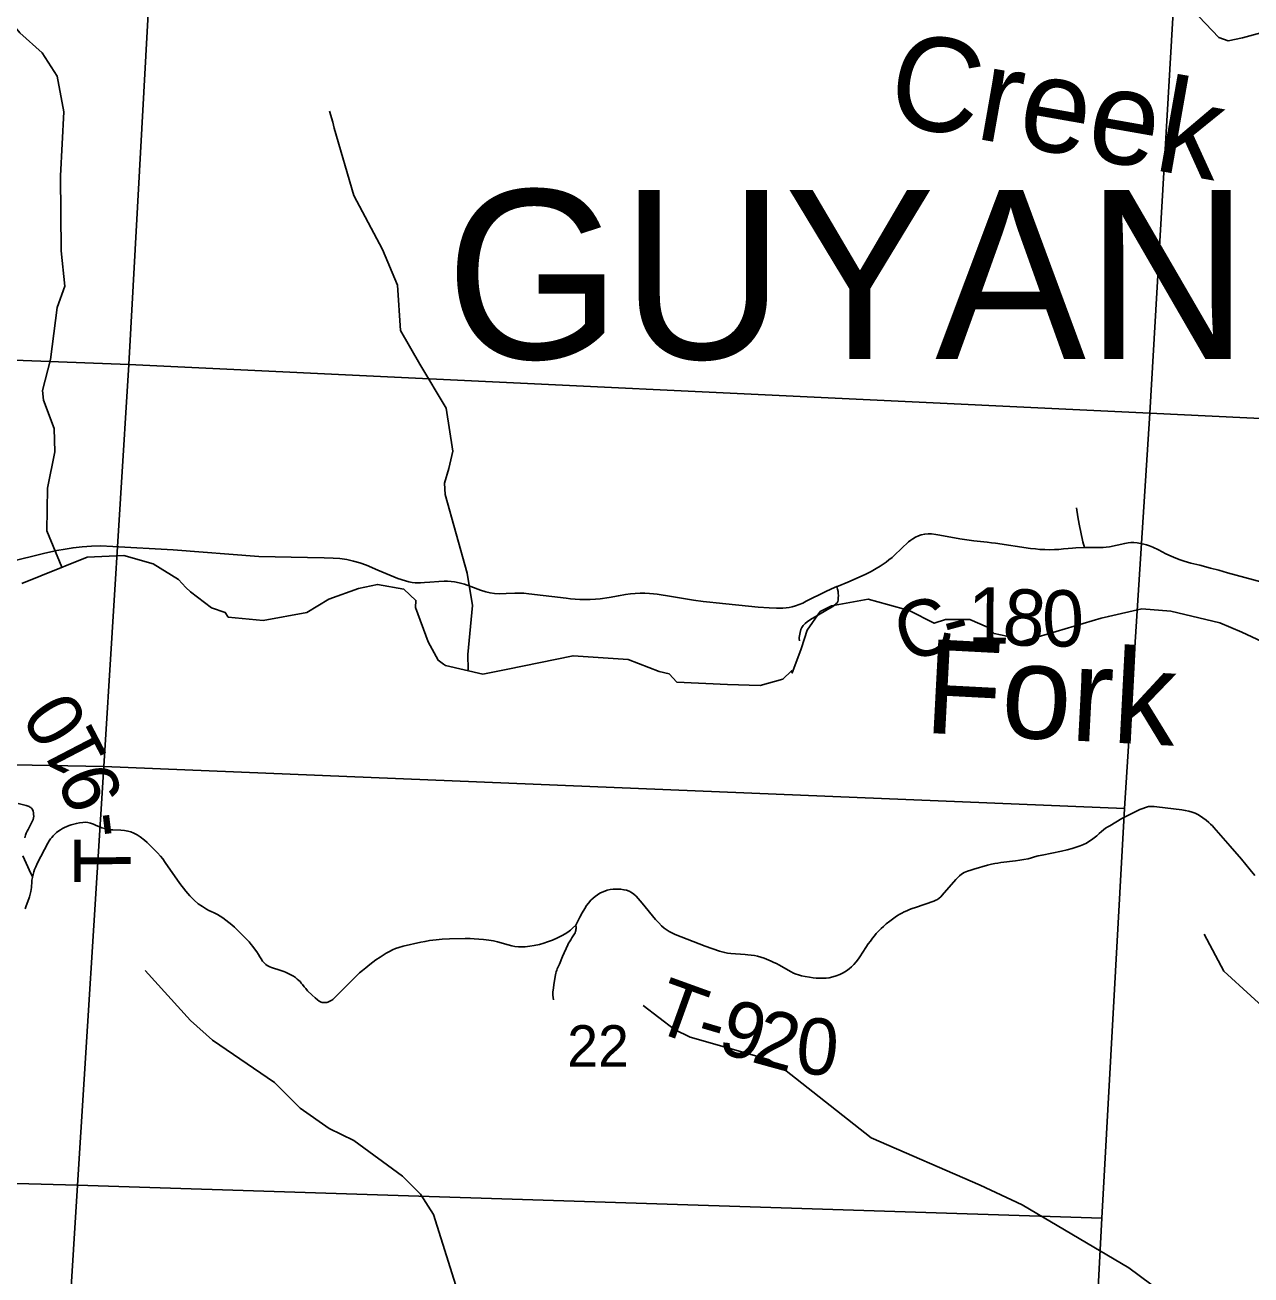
# Model space of a CAD drawing. Extents: x 0 to 34, y 0 to 22.
# Drawn here: x 25.071 to 26.308, y 17.66 to 18.921 of the extents above; entities that cross this region are included whole.
import ezdxf

# ---------------------------------------------------------------- set-up
doc = ezdxf.new("R2010")
doc.units = 0
for name, color, linetype in [('GM_X_County_Road', 7, 'Continuous'), ('GM_X_County_Road_Text', 7, 'Continuous'), ('GM_X_Minor_River', 7, 'Continuous'), ('GM_X_Minor_River_Text', 7, 'Continuous'), ('GM_X_Section', 7, 'Continuous'), ('GM_X_Section_Text', 7, 'Continuous'), ('GM_X_Township_Road', 7, 'Continuous'), ('GM_X_Township_Road_Text', 7, 'Continuous'), ('GM_X_Township_Text', 7, 'Continuous')]:
    doc.layers.add(name, color=color, linetype=linetype)

msp = doc.modelspace()

# ---------------------------------------------------------------- linework, layer by layer
at = {"layer": 'GM_X_County_Road'}
for points in [[(25.3731, 18.3836), (25.3822, 18.3832), (25.3889, 18.3827), (25.396, 18.3818), (25.4027, 18.3802), (25.4091, 18.3783), (25.4161, 18.3759), (25.4275, 18.371), (25.4476, 18.3627), (25.4553, 18.3602), (25.4586, 18.3594), (25.462, 18.3586), (25.4651, 18.3583), (25.4679, 18.3581), (25.4705, 18.3582), (25.4743, 18.3584), (25.48, 18.3588), (25.4888, 18.3596), (25.4943, 18.3599), (25.4975, 18.3599), (25.5012, 18.3597), (25.5046, 18.3592), (25.5094, 18.3583), (25.5147, 18.3568), (25.5211, 18.3546), (25.531, 18.3507), (25.5363, 18.349), (25.5406, 18.3481), (25.545, 18.3475), (25.55, 18.3472), (25.5569, 18.3474), (25.5656, 18.3479), (25.5703, 18.3479), (25.5748, 18.3477), (25.5797, 18.3472), (25.6173, 18.3426), (25.6217, 18.3422), (25.6265, 18.3417), (25.6313, 18.3415), (25.6369, 18.3414), (25.6416, 18.3414), (25.6468, 18.3416), (25.6517, 18.3421), (25.6608, 18.3435), (25.67, 18.3452), (25.6773, 18.3464), (25.6824, 18.3471), (25.6871, 18.3475), (25.6919, 18.3478), (25.6966, 18.3478), (25.7013, 18.3476), (25.7054, 18.3472), (25.7092, 18.3467), (25.7236, 18.3444), (25.7459, 18.3409), (25.7554, 18.3395), (25.7623, 18.3387), (25.7685, 18.338), (25.8109, 18.3338), (25.822, 18.3331), (25.8294, 18.3327), (25.8324, 18.3327), (25.8359, 18.3328), (25.8393, 18.3331), (25.8424, 18.3335), (25.8454, 18.334), (25.8487, 18.335), (25.8523, 18.3362), (25.856, 18.3378), (25.8595, 18.3396), (25.8794, 18.3495), (25.8843, 18.3519), (25.8882, 18.3536), (25.8905, 18.3545), (25.8919, 18.355), (25.9015, 18.3588), (25.9188, 18.3666), (25.9249, 18.3698), (25.9302, 18.3727), (25.9341, 18.375), (25.937, 18.377), (25.94, 18.3791), (25.943, 18.3813), (25.9461, 18.3837), (25.9486, 18.386), (25.9628, 18.3995), (25.9649, 18.4012), (25.9669, 18.4026), (25.9696, 18.4044), (25.9727, 18.4058), (25.9756, 18.4068), (25.979, 18.4074), (25.9825, 18.4076), (25.986, 18.4075), (25.9902, 18.407), (25.9944, 18.4062), (26.0146, 18.4025), (26.0287, 18.4006), (26.0419, 18.3992), (26.0463, 18.3987), (26.0505, 18.3981), (26.0856, 18.3929), (26.0908, 18.3924), (26.0953, 18.392), (26.1001, 18.3917), (26.1052, 18.3916), (26.1099, 18.3917), (26.1144, 18.392), (26.1191, 18.3924), (26.1239, 18.393), (26.1282, 18.3933), (26.1316, 18.3936), (26.1401, 18.3938), (26.156, 18.3939), (26.159, 18.394), (26.1622, 18.3943), (26.1654, 18.3947), (26.1808, 18.398), (26.1841, 18.3985), (26.1871, 18.3988), (26.19, 18.3988), (26.1932, 18.3985), (26.1968, 18.398), (26.2, 18.3973), (26.2028, 18.3965), (26.2058, 18.3954), (26.209, 18.3942), (26.2147, 18.3916), (26.2223, 18.3876), (26.2278, 18.385), (26.2323, 18.3831), (26.2366, 18.3815), (26.2408, 18.38), (26.2475, 18.3782), (26.2564, 18.376), (26.2673, 18.3731), (26.2756, 18.3709), (26.2845, 18.3684), (26.3282, 18.3564)], [(25.056, 18.3795), (25.0902, 18.3878), (25.1035, 18.3907), (25.112, 18.3923), (25.12, 18.3937), (25.1292, 18.3947), (25.1384, 18.3953), (25.1477, 18.3954), (25.1601, 18.395), (25.2208, 18.3915), (25.3075, 18.3848), (25.3566, 18.3838), (25.3731, 18.3836)]]:
    msp.add_lwpolyline(points, dxfattribs=at)
at = {"layer": 'GM_X_Minor_River'}
for points in [[(25.1087, 18.3739), (25.0935, 18.4107), (25.0941, 18.4539), (25.1016, 18.4905), (25.1008, 18.5141), (25.09, 18.5425), (25.0891, 18.5524), (25.0973, 18.5837), (25.1038, 18.6359), (25.1116, 18.6577), (25.1078, 18.6931), (25.1074, 18.769), (25.1105, 18.8335), (25.104, 18.8694), (25.0889, 18.893), (25.0661, 18.9131), (25.0493, 18.9338), (25.0384, 18.9611), (25.0367, 18.9657), (25.0297, 19.0217), (25.0166, 19.0525), (25.0135, 19.0633)], [(26.3404, 18.9193), (26.2996, 18.9082), (26.2852, 18.9051), (26.2758, 18.9085), (26.2557, 18.9297)], [(25.5184, 18.2704), (25.518, 18.286), (25.5229, 18.3355), (25.5175, 18.368), (25.4953, 18.4473), (25.4945, 18.4587), (25.4991, 18.4737), (25.5031, 18.4911), (25.4964, 18.5346), (25.4698, 18.5787), (25.4501, 18.6127), (25.4473, 18.6584), (25.4321, 18.6946), (25.4032, 18.749), (25.3833, 18.8169), (25.382, 18.823), (25.3785, 18.8341)], [(26.3387, 18.2899), (26.299, 18.3085), (26.2767, 18.3179), (26.2272, 18.3296), (26.1981, 18.3321), (26.1644, 18.3244), (26.1569, 18.3225), (26.0934, 18.3037), (26.0733, 18.298), (26.062, 18.3044), (26.0491, 18.307), (26.0423, 18.3135), (26.0246, 18.3214), (26, 18.3214), (25.9887, 18.3175), (25.9633, 18.3304), (25.9414, 18.3364), (25.9221, 18.3417), (25.8851, 18.3351), (25.8737, 18.3294), (25.8605, 18.3104), (25.8549, 18.2925), (25.8541, 18.2906), (25.8454, 18.2674), (25.8447, 18.2696), (25.836, 18.2609), (25.8129, 18.2547), (25.78, 18.2558), (25.729, 18.2579), (25.7214, 18.2663), (25.7112, 18.2689), (25.6799, 18.281), (25.6243, 18.2846), (25.557, 18.2708), (25.5332, 18.2662), (25.4958, 18.2748), (25.4935, 18.2763), (25.4882, 18.2801), (25.478, 18.2987), (25.4655, 18.3332), (25.4658, 18.3405), (25.4537, 18.3518), (25.4269, 18.3567), (25.408, 18.3525), (25.3781, 18.3418), (25.3559, 18.3284), (25.3116, 18.3203), (25.2765, 18.3236), (25.2734, 18.3282), (25.2595, 18.3331), (25.2383, 18.349), (25.2337, 18.3536), (25.2262, 18.3615), (25.2008, 18.3774), (25.1713, 18.3857), (25.1343, 18.3841), (25.0874, 18.3653), (25.0682, 18.3577)], [(26.6717, 17.3353), (26.6812, 17.3584), (26.6822, 17.3762), (26.6747, 17.417), (26.664, 17.4496), (26.6499, 17.5215), (26.635, 17.5519), (26.6181, 17.5692), (26.6045, 17.5825), (26.5893, 17.6157), (26.5642, 17.637), (26.5403, 17.6723), (26.4513, 17.7909), (26.4148, 17.8437), (26.3814, 17.8649), (26.3697, 17.8778), (26.3662, 17.887), (26.3625, 17.8917), (26.2809, 17.9664), (26.2609, 18.0039)], [(25.5382, 17.5003), (25.5308, 17.5239), (25.5311, 17.5706), (25.5238, 17.605), (25.5135, 17.6258), (25.4835, 17.7209), (25.4705, 17.7415), (25.4521, 17.7595), (25.4033, 17.7956), (25.3784, 17.8078), (25.3491, 17.8281), (25.3231, 17.854), (25.2605, 17.8969), (25.2384, 17.9166), (25.1927, 17.9671)], [(26.2068, 17.204), (26.2214, 17.2242), (26.236, 17.2634), (26.2386, 17.3906), (26.2407, 17.4301), (26.2458, 17.4552), (26.2716, 17.5168), (26.2691, 17.5559), (26.2564, 17.5946), (26.2338, 17.6256), (26.2189, 17.6418), (26.185, 17.6671), (26.0772, 17.7307), (26.0349, 17.7505), (25.925, 17.7982), (25.8376, 17.8672), (25.8216, 17.8773), (25.7426, 17.8997), (25.7266, 17.9076), (25.6949, 17.9317)]]:
    msp.add_lwpolyline(points, dxfattribs=at)
at = {"layer": 'GM_X_Section'}
for points in [[(24.2052, 19.6482), (25.2325, 19.5985), (25.1763, 18.5784), (24.1456, 18.6175)], [(25.2325, 19.5985), (26.2655, 19.5533), (26.2062, 18.5294), (25.1763, 18.5784)], [(26.2655, 19.5533), (27.3196, 19.501), (27.254, 18.479), (26.2062, 18.5294)], [(24.1456, 18.6175), (25.1763, 18.5784), (25.1509, 18.1729), (24.1185, 18.1922)], [(25.1763, 18.5784), (26.2062, 18.5294), (26.1806, 18.1307), (25.1509, 18.1729)], [(26.2062, 18.5294), (27.254, 18.479), (27.228, 18.0601), (27.2029, 17.6387), (27.1952, 17.4804), (26.5953, 17.5088), (26.1481, 17.5351), (26.1482, 17.5386), (26.1578, 17.7173), (26.1806, 18.1307)], [(25.1509, 18.1729), (25.1245, 17.7506), (24.0951, 17.7788), (24.1185, 18.1922)], [(25.1509, 18.1729), (26.1806, 18.1307), (26.1578, 17.7173), (25.1245, 17.7506)], [(24.0951, 17.7788), (25.1245, 17.7506), (25.1122, 17.5559), (24.0818, 17.5731)], [(25.1245, 17.7506), (26.1578, 17.7173), (26.1482, 17.5386), (25.1122, 17.5559)]]:
    msp.add_lwpolyline(points, close=True, dxfattribs=at)
at = {"layer": 'GM_X_Township_Road'}
for points in [[(26.1401, 18.3938), (26.1387, 18.3996), (26.1349, 18.4173), (26.1336, 18.4248), (26.1322, 18.4338)], [(25.8526, 18.2996), (25.8524, 18.3019), (25.8525, 18.3032), (25.8533, 18.3081), (25.8541, 18.3111), (25.8552, 18.3133), (25.8565, 18.3153), (25.8584, 18.3172), (25.8606, 18.3189), (25.8638, 18.3211), (25.8701, 18.325), (25.8793, 18.3302), (25.8864, 18.3345), (25.8885, 18.336), (25.8895, 18.3369), (25.8906, 18.3381), (25.8913, 18.3393), (25.8916, 18.3409), (25.8919, 18.343), (25.892, 18.3456), (25.8918, 18.3476), (25.8916, 18.3496), (25.8911, 18.3518), (25.8905, 18.3545)], [(25.0712, 18.1008), (25.0716, 18.1024), (25.072, 18.1037), (25.0728, 18.1055), (25.0737, 18.1076), (25.0747, 18.1095), (25.0792, 18.118), (25.0797, 18.1195), (25.0801, 18.121), (25.0803, 18.1227), (25.0802, 18.1244), (25.0801, 18.1261), (25.0796, 18.1278), (25.0789, 18.1295), (25.0779, 18.1308), (25.0772, 18.1314), (25.0765, 18.1319), (25.0756, 18.1324), (25.0747, 18.1328), (25.0737, 18.1331), (25.0728, 18.1334), (25.0646, 18.1355)], [(25.0715, 18.0294), (25.0728, 18.0325), (25.0754, 18.0394), (25.076, 18.0414), (25.0767, 18.0442), (25.0774, 18.0468), (25.0777, 18.0489), (25.078, 18.0508), (25.0781, 18.0525), (25.0782, 18.0551), (25.0785, 18.0582), (25.079, 18.0608), (25.0792, 18.0619), (25.0797, 18.064), (25.0804, 18.0666), (25.0812, 18.069), (25.0823, 18.0718), (25.0842, 18.0757), (25.0945, 18.0956), (25.0959, 18.0979), (25.0972, 18.0998), (25.0984, 18.1014), (25.0999, 18.103), (25.1013, 18.1044), (25.1034, 18.1064), (25.1056, 18.108), (25.1073, 18.1091), (25.1093, 18.1103), (25.1113, 18.1113), (25.1135, 18.1124), (25.116, 18.1135), (25.1182, 18.1142), (25.1208, 18.1149), (25.1234, 18.1155), (25.1265, 18.1161), (25.1297, 18.1165), (25.1321, 18.1167), (25.1348, 18.1165), (25.1376, 18.1157), (25.1404, 18.1146), (25.1431, 18.1134), (25.1459, 18.1123), (25.149, 18.1112), (25.152, 18.1103), (25.1545, 18.1096), (25.1572, 18.1091), (25.1599, 18.1089), (25.1683, 18.1086), (25.1719, 18.1083), (25.1753, 18.1077), (25.1783, 18.1069), (25.1814, 18.1058), (25.1846, 18.1041), (25.1878, 18.1019), (25.1919, 18.0986), (25.1948, 18.0961), (25.1987, 18.0923), (25.2021, 18.0889), (25.2051, 18.0858), (25.2082, 18.0823), (25.2104, 18.0796), (25.213, 18.0762), (25.2277, 18.0547), (25.2337, 18.047), (25.2377, 18.0424), (25.2421, 18.038), (25.2463, 18.0344), (25.2504, 18.0316), (25.2546, 18.029), (25.2569, 18.0277), (25.2593, 18.0266), (25.2623, 18.0252), (25.2655, 18.0235), (25.2684, 18.0219), (25.2711, 18.0201), (25.2742, 18.0179), (25.2772, 18.0156), (25.2802, 18.0131), (25.2827, 18.0108), (25.2858, 18.0078), (25.2888, 18.0049), (25.292, 18.0017), (25.2952, 17.9984), (25.2975, 17.9959), (25.2997, 17.9933), (25.3014, 17.9912), (25.3031, 17.9889), (25.3052, 17.9858), (25.307, 17.9832), (25.3085, 17.9809), (25.3097, 17.9788), (25.3111, 17.9766), (25.3127, 17.9747), (25.3145, 17.9731), (25.3157, 17.9722), (25.317, 17.9714), (25.3185, 17.9707), (25.32, 17.9702), (25.3222, 17.9694), (25.3274, 17.9677), (25.3324, 17.966), (25.3343, 17.9654), (25.3363, 17.9645), (25.3383, 17.9634), (25.3403, 17.9624), (25.3422, 17.9613), (25.3442, 17.96), (25.3461, 17.9585), (25.3478, 17.957), (25.349, 17.9559), (25.3502, 17.9544), (25.3513, 17.953), (25.353, 17.9507), (25.3546, 17.9488), (25.3565, 17.9466), (25.361, 17.9423), (25.364, 17.9395), (25.3666, 17.9374), (25.3683, 17.9361), (25.3702, 17.9352), (25.3713, 17.9349), (25.3724, 17.9348), (25.3735, 17.9347), (25.3745, 17.9348), (25.3758, 17.9349), (25.3768, 17.9351), (25.3783, 17.9357), (25.3797, 17.9364), (25.3809, 17.9371), (25.382, 17.9378), (25.3831, 17.9387), (25.3905, 17.9462), (25.409, 17.9646), (25.4119, 17.9671), (25.4152, 17.9697), (25.4194, 17.973), (25.4255, 17.9777), (25.4296, 17.9805), (25.4328, 17.9826), (25.4359, 17.9845), (25.439, 17.9863), (25.4422, 17.9879), (25.4452, 17.9892), (25.4486, 17.9904), (25.4531, 17.9916), (25.4708, 17.9956), (25.475, 17.9964), (25.4796, 17.9972), (25.4861, 17.9981), (25.4923, 17.9986), (25.4998, 17.9989), (25.5155, 17.9993), (25.5204, 17.9993), (25.5247, 17.9991), (25.5294, 17.9988), (25.5341, 17.9984), (25.5392, 17.9977), (25.5442, 17.9969), (25.5481, 17.996), (25.5517, 17.995), (25.5552, 17.994), (25.5589, 17.9929), (25.5624, 17.992), (25.5657, 17.9914), (25.5693, 17.991), (25.5726, 17.9909), (25.5761, 17.9911), (25.5807, 17.9915), (25.585, 17.9922), (25.5906, 17.9934), (25.5947, 17.9946), (25.5986, 17.9959), (25.6036, 17.9978), (25.6086, 18), (25.6134, 18.0023), (25.6163, 18.004), (25.619, 18.0057), (25.6217, 18.0078), (25.6239, 18.0098), (25.6272, 18.0129), (25.6313, 18.021), (25.6335, 18.0254), (25.6361, 18.0298), (25.638, 18.0327), (25.6399, 18.0351), (25.6424, 18.0379), (25.6446, 18.0402), (25.6467, 18.0419), (25.6489, 18.0436), (25.6513, 18.0451), (25.6537, 18.0462), (25.6562, 18.0472), (25.6588, 18.0482), (25.6618, 18.0488), (25.6648, 18.0492), (25.6675, 18.0492), (25.67, 18.0492), (25.6725, 18.049), (25.6756, 18.0486), (25.6783, 18.048), (25.6809, 18.047), (25.6834, 18.0457), (25.6856, 18.0441), (25.6879, 18.0421), (25.69, 18.0398), (25.692, 18.0375), (25.694, 18.0351), (25.7075, 18.0187), (25.7108, 18.0151), (25.7136, 18.0122), (25.7163, 18.0099), (25.7191, 18.0077), (25.7214, 18.0063), (25.7238, 18.005), (25.7273, 18.0035), (25.7577, 17.9918), (25.7721, 17.9867), (25.7747, 17.9859), (25.7774, 17.9851), (25.7801, 17.9847), (25.7836, 17.9843), (25.7979, 17.9833), (25.8007, 17.983), (25.804, 17.9826), (25.8072, 17.9821), (25.8105, 17.9814), (25.8138, 17.9805), (25.817, 17.9794), (25.8243, 17.9765), (25.8269, 17.9753), (25.8294, 17.974), (25.8318, 17.9727), (25.8444, 17.9657), (25.8466, 17.9645), (25.8492, 17.9634), (25.8518, 17.9626), (25.8549, 17.9617), (25.8586, 17.961), (25.8629, 17.9603), (25.8664, 17.9598), (25.8694, 17.9594), (25.8727, 17.9592), (25.8759, 17.9592), (25.8796, 17.9594), (25.8827, 17.9598), (25.8862, 17.9606), (25.8896, 17.9617), (25.8935, 17.9632), (25.8969, 17.9649), (25.9003, 17.9669), (25.9028, 17.9688), (25.9053, 17.9709), (25.9076, 17.9731), (25.91, 17.9759), (25.9121, 17.9787), (25.9137, 17.9808), (25.9197, 17.9902), (25.922, 17.9939), (25.9242, 17.9968), (25.9263, 17.9997), (25.9283, 18.0022), (25.9302, 18.0044), (25.9324, 18.0067), (25.935, 18.0093), (25.9373, 18.0114), (25.9403, 18.0141), (25.9438, 18.0169), (25.9465, 18.019), (25.9492, 18.021), (25.9516, 18.0225), (25.9539, 18.0239), (25.956, 18.025), (25.9583, 18.0262), (25.9611, 18.0274), (25.9636, 18.0285), (25.9665, 18.0295), (25.9696, 18.0306), (25.9883, 18.0372), (25.9904, 18.038), (25.992, 18.0388), (25.9937, 18.04), (25.9952, 18.0415), (25.9967, 18.043), (26.0104, 18.0589), (26.0121, 18.0607), (26.0141, 18.0626), (26.0162, 18.0642), (26.019, 18.0658), (26.0222, 18.0673), (26.0254, 18.0684), (26.0286, 18.0694), (26.0424, 18.0734), (26.0463, 18.0743), (26.0497, 18.075), (26.0527, 18.0755), (26.0559, 18.0759), (26.0707, 18.0779), (26.075, 18.0785), (26.0789, 18.0791), (26.0833, 18.0799), (26.0867, 18.0807), (26.0899, 18.0818), (26.0934, 18.0827), (26.0974, 18.0836), (26.117, 18.0876), (26.1227, 18.089), (26.1278, 18.0903), (26.1318, 18.0916), (26.1358, 18.093), (26.1391, 18.0942), (26.1421, 18.0957), (26.1447, 18.0971), (26.1473, 18.0988), (26.15, 18.1009), (26.1527, 18.1031), (26.155, 18.1052), (26.1574, 18.1072), (26.1595, 18.109), (26.1615, 18.1106), (26.1636, 18.1119), (26.1658, 18.1132), (26.178, 18.1204), (26.1934, 18.1283), (26.1962, 18.1296), (26.1989, 18.1307), (26.2019, 18.1317), (26.2049, 18.1324), (26.2077, 18.1327), (26.2105, 18.1326), (26.2132, 18.1323), (26.2383, 18.1291), (26.2418, 18.1286), (26.2455, 18.1279), (26.2487, 18.127), (26.2517, 18.1258), (26.2546, 18.1244), (26.2571, 18.1228), (26.2596, 18.1211), (26.2629, 18.1186), (26.2655, 18.1164), (26.2674, 18.1147), (26.2693, 18.113), (26.2708, 18.1113), (26.287, 18.0924), (26.2985, 18.0793), (26.3073, 18.0686), (26.3121, 18.0629)], [(25.0792, 18.0619), (25.0775, 18.0648), (25.0727, 18.0754), (25.0694, 18.0828)], [(25.6046, 17.9376), (25.6039, 17.9421), (25.6038, 17.9438), (25.6039, 17.9456), (25.6042, 17.9474), (25.6054, 17.9549), (25.6067, 17.9626), (25.6071, 17.9644), (25.6074, 17.9659), (25.6079, 17.9674), (25.6084, 17.9687), (25.6105, 17.9735), (25.6138, 17.9811), (25.619, 17.9929), (25.6198, 17.9945), (25.6206, 17.9959), (25.6219, 17.9979), (25.6232, 18.0001), (25.6257, 18.0042), (25.6263, 18.0052), (25.6268, 18.0064), (25.6271, 18.0076), (25.6272, 18.0085), (25.6273, 18.0093), (25.6273, 18.0108), (25.6272, 18.0129)]]:
    msp.add_lwpolyline(points, dxfattribs=at)

# ---------------------------------------------------------------- texts
at = {"layer": 'GM_X_County_Road_Text'}
for s, rotation, p in [('1', 359.5811, (26.0223, 18.2971)), ('8', 354.6607, (26.056, 18.2969)), ('0', 1.4818, (26.0982, 18.2934)), ('C', 18.9515, (25.9606, 18.2767)), ('-', 14.9583, (26.0037, 18.2916))]:
    msp.add_text(s, height=0.0568, rotation=rotation, dxfattribs=at).set_placement(p)
at = {"layer": 'GM_X_Minor_River_Text'}
for s, rotation, p in [('Creek', 350.0126, (25.9383, 18.8226)), ('Fork', 357.013, (25.9775, 18.207))]:
    msp.add_text(s, height=0.09469, rotation=rotation, dxfattribs=at).set_placement(p)
at = {"layer": 'GM_X_Section_Text'}
msp.add_text('22', height=0.04186, rotation=0, dxfattribs=at).set_placement((25.6184, 17.87))
at = {"layer": 'GM_X_Township_Road_Text'}
for s, rotation, p in [('0', 122.7891, (25.137, 18.2176)), ('1', 117.4816, (25.156, 18.1815)), ('9', 110.2775, (25.1713, 18.1416)), ('-', 97.1054, (25.1776, 18.1046)), ('T', 90.2571, (25.1782, 18.0548)), ('T', 340.1352, (25.7021, 17.9075)), ('9', 343.8492, (25.7683, 17.8853)), ('2', 344.5951, (25.8027, 17.8753)), ('-', 343.5921, (25.7457, 17.8919)), ('0', 354.9875, (25.8475, 17.864))]:
    msp.add_text(s, height=0.0568, rotation=rotation, dxfattribs=at).set_placement(p)
at = {"layer": 'GM_X_Township_Text'}
msp.add_text('GUYAN', height=0.17045, rotation=0, dxfattribs=at).set_placement((25.4957, 18.5842))

doc.saveas('drawing.dxf')
